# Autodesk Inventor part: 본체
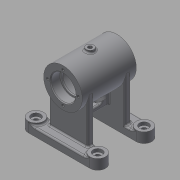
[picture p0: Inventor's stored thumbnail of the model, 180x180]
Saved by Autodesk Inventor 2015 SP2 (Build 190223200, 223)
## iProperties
Created: 2015-11
Part Number: 본체
Material: 일반
Document SubType Name: Modeling
Designer: AMC
Density: 1 g/cm^3
Appearance: 기본값
Author: AMC
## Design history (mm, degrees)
sketch "스케치1"
  geometry: L1 (-40, 40)-(40, 40); L2 (40, 40)-(40, 20); L3 (40, 20)-(-40, 20); L4 (-40, 20)-(-40, 40); L5 (-40, -40)-(40, -40); L6 (40, -40)-(40, -20); L7 (40, -20)-(-40, -20); L8 (-40, -20)-(-40, -40); L9 (-5, -20)-(5, -20); L10 (5, -20)-(5, 20); L11 (5, 20)-(-5, 20); L12 (-5, 20)-(-5, -20); L13 (-5, -20)-(5, 20); L14 (5, -20)-(-5, 20); C1 r 10 at (40, -30); 6 further points
  constraints: 28 end point, 10 midpoint, 6 parallel, 3 horizontal, 3 perpendicular, 3 vertical alignment, 1 centre point, 1 tangent, 6 other
  dimensions: "d8" = 80 distance of L2.end L3.end; "d9" = 20 distance of L1.end L2.end; "d10" = 80 distance of L7.end L6.end; "d11" = 20 distance of L6.end L5.end
extrude "돌출1" new body sketch "스케치1" distance "d14" = 10; taper "d15" = 0 deg
extrude "돌출2" join sketch "스케치1" distance "d16" = 13; taper "d17" = 0 deg
sketch "스케치2"
  geometry: L1 (-25, -20)-(25, -20); L2 (25, -20)-(25, -28); L3 (25, -28)-(-25, -28); L4 (-25, -28)-(-25, -20); L5 (-25, -20)-(25, -28); L6 (25, -20)-(-25, -28); L7 (-25, 28)-(25, 28); L8 (25, 28)-(25, 20); L9 (25, 20)-(-25, 20); L10 (-25, 20)-(-25, 28); L11 (-25, 28)-(25, 20); L12 (25, 28)-(-25, 20); L13 (40, -20)-(-40, -20) reference; L14 (40, 20)-(-40, 20) reference; 5 further points
  constraints: 24 end point, 8 midpoint, 4 parallel, 2 horizontal, 2 perpendicular
  dimensions: "d18" = 50 distance of L2.end L3.end; "d19" = 8 distance of L1.end L2.end; "d20" = 50 distance of L8.end L9.end; "d21" = 8 distance of L7.end L8.end
extrude "돌출3" join sketch "스케치2" distance "d22" = 58; taper "d23" = 0 deg
sketch "스케치3"
  geometry: C1 r 25 at (0, 68); 1 further point
  constraints: 1 centre point
  dimensions: "d24" = 50 diameter of C1
extrude "돌출4" join sketch "스케치3" stored distance "d25" = 70; taper "d26" = 0 deg
sketch "스케치4"
  geometry: C1 r 16 at (0, 0); 1 further point
  constraints: 1 centre point
  dimensions: "d27" = 32 diameter of C1
extrude "돌출5" cut sketch "스케치4" distance "d28" = 12; taper "d29" = 0 deg
sketch "스케치5"
  geometry: C1 r 14 at (0, 0); 1 further point
  constraints: 1 centre point
  dimensions: "d30" = 28 diameter of C1
extrude "돌출6" cut sketch "스케치5" distance "d31" = 2; taper "d32" = 0 deg
sketch "스케치6"
  geometry: C1 r 21 at (0, 68); 1 further point
  constraints: 1 centre point
  dimensions: "d33" = 42 diameter of C1
extrude "돌출7" cut sketch "스케치6" stored distance "d34" = 42; taper "d35" = 0 deg
sketch "스케치7"
  geometry: C1 r 6 at (0, 0); C2 r 3 at (0, 0); 1 further point
  constraints: 2 centre point, 1 coincident
  dimensions: "d36" = 12 diameter of C1; "d37" = 6 diameter of C2
extrude "돌출8" cut sketch "스케치7" distance "d38" = 13; taper "d39" = 0 deg
extrude "돌출9" cut sketch "스케치7" distance "d40" = 4; taper "d41" = 0 deg
sketch "스케치8"
  geometry: L1 (44, -43)-(36, -43); L2 (36, -43)-(36, -23); L3 (36, -23)-(44, -23); L4 (44, -23)-(44, -43); L5 (44, -43)-(36, -23); L6 (36, -43)-(44, -23); A1 r 25 centre (40, -68) between (65, -68) and (15, -68) reference; 4 further points
  constraints: 12 end point, 3 midpoint, 2 coincident, 2 parallel, 1 horizontal, 1 perpendicular, 1 point on circle
  dimensions: "d42" = 8 distance of L2.end L3.end; "d43" = 20 distance of L1.end L2.end
extrude "돌출10" join sketch "스케치8" stored distance "d44" = 4; taper "d45" = 0 deg
chamfer "모따기1" distance "d46" = 1; stored, may be unused: second distance "d47" = 2, angle "d48" = 45 deg
fillet "모깎기1" dims "d49" = 3
fillet "모깎기2" dims "d50" = 0.3
sketch "스케치9"
  geometry: L1 (10, 8.5)-(10, 8.5); L2 (13.5, 12)-(13.5, 28); L3 (10, 31.5)-(10, 31.5); L4 (6.5, 28)-(6.5, 12); L5 (6.5, 8.5)-(13.5, 31.5); L6 (13.5, 8.5)-(6.5, 31.5); L7 (0, 0)-(20, 0); L8 (10, 0)-(10, 40); A1 r 3.5 centre (10, 12) between (10, 8.5) and (13.5, 12); A2 r 3.5 centre (10, 12) between (6.5, 12) and (10, 8.5); A3 r 3.5 centre (10, 28) between (10, 31.5) and (6.5, 28); A4 r 3.5 centre (10, 28) between (13.5, 28) and (10, 31.5); 1 further point
  constraints: 16 end point, 8 point on circle, 8 point on line, 8 tangent, 4 centre point, 4 midpoint, 3 equal radius, 2 horizontal, 2 parallel, 1 perpendicular, 1 vertical
  dimensions: "d51" = 7 distance of L6.end L5.end; "d52" = 23 distance of L5.end L6.start; "d55" = 3.5 radius of A1
extrude "돌출11" cut sketch "스케치9" distance "d56" = 8; taper "d57" = 0 deg
fillet "모깎기3" dims "d58" = 2
fillet "모깎기4" dims "d59" = 2
fillet "모깎기5" dims "d60" = 2
sketch "스케치10"
  geometry: L1 (0, 68)-(0, 96); L2 (0, 68)-(-14, 43.751); 1 further point
  constraints: 4 end point, 1 vertical
  dimensions: "d62" = 28 distance of L1.start L2.end; "d63" = 30 deg angle of L2 L1
node "작업 평면1"
sketch "스케치11"
  geometry: C1 r 5 at (0, 0); 1 further point
  constraints: 1 centre point, 1 coincident
  dimensions: "d64" = 10 diameter of C1
extrude "돌출12" join sketch "스케치11" distance "d65" = 4; taper "d66" = 0 deg
node "작업 평면2"
sketch "스케치12"
  geometry: C1 r 6 at (0, 0); 1 further point
  constraints: 1 centre point
  dimensions: "d67" = 12 diameter of C1
extrude "돌출13" join sketch "스케치12" distance "d68" = 6; taper "d69" = 0 deg
hole "구멍1" diameter "d72" = 4.917; stored, may be unused: countersink angle "d76" = 90 deg, drill point angle "d78" = 118 deg; dims "d73" = 12, "d74" = 4, "d75" = 2, "d77" = 17, "d88" = 10, "d89" = 10
hole "구멍2" diameter "d81" = 4.917; stored, may be unused: countersink angle "d85" = 90 deg, drill point angle "d87" = 118 deg; dims "d79" = 10, "d80" = 10, "d82" = 12, "d83" = 4, "d84" = 2, "d86" = 17
fillet "모깎기6" dims "d90" = 2
fillet "모깎기7" dims "d91" = 2
node "작업 평면3"
sketch "스케치13"
  geometry: L1 (-20.739, -5.707)-(20.739, -5.707); L2 (20.739, -5.707)-(20.739, 5.707); L3 (20.739, 5.707)-(-20.739, 5.707); L4 (-20.739, 5.707)-(-20.739, -5.707); L5 (-20.739, 0)-(20.739, 0); L6 (0, -5.707)-(0, 5.707); L7 (-35, 25)-(-35, -25) reference; 1 further point
  constraints: 5 midpoint, 4 end point, 2 other
  dimensions: "d92" = 35 distance from line of L7 point (0, 0)
feature "엠보싱1" sketch "스케치13" dims "d94" = 0.5, "d95" = 0
sketch "스케치14" dims "d96" = 40
  geometry: 3 further points
  constraints: 1 vertical alignment, 2 other
hole "구멍3" sketch "스케치14" at (0, 20) diameter "d97" = 3.242; stored, may be unused: countersink angle "d101" = 90 deg, drill point angle "d103" = 118 deg; dims "d98" = 8, "d99" = 4, "d100" = 2, "d102" = 10
fillet "모깎기8" dims "d107" = 2
fillet "모깎기9" dims "d108" = 2
fillet "모깎기10" dims "d109" = 2
node "솔리드1"
mirror "대칭1"
mirror "대칭2"
mirror "대칭3"
pattern_circular "원형 패턴1" dims angle "d105" = 360 deg
mirror "대칭4"
